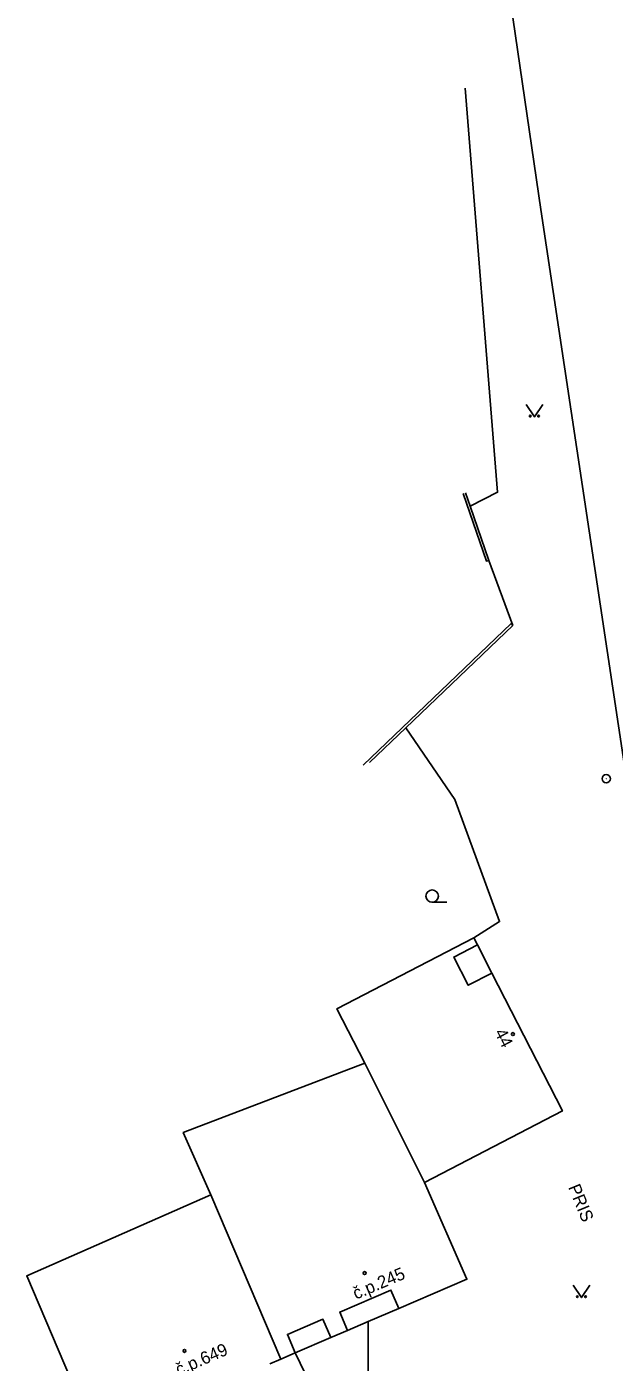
# Model space of a CAD drawing. Extents: x -577457 to -568404, y -1208466 to -1201387.
# Drawn here: x -574806.3 to -574771, y -1204115.5 to -1204035.2 of the extents above; entities that cross this region are included whole.
import ezdxf

# ---------------------------------------------------------------- set-up
doc = ezdxf.new("R2010")
doc.units = 0
for name, color, linetype in [('BUDOVY_MĚŘ', 7, 'Continuous'), ('BUDOVY_NEMĚŘ', 7, 'Continuous'), ('POMOC_POPIS', 7, 'Continuous'), ('ROZHRANÍ_PLOCH', 7, 'Continuous'), ('ZN_BUDOV', 7, 'Continuous'), ('ZN_DOPLŇKOVÉ', 7, 'Continuous'), ('ZN_KULTUR', 7, 'Continuous'), ('Č_POPIS_ORIENT', 7, 'Continuous')]:
    doc.layers.add(name, color=color, linetype=linetype)

msp = doc.modelspace()

# ---------------------------------------------------------------- linework, layer by layer
at = {"layer": 'BUDOVY_MĚŘ'}
for points in [[(-574779.19, -1204090.44), (-574780.62, -1204091.17), (-574779.75, -1204092.86), (-574778.33, -1204092.13)], [(-574779.41, -1204090.02), (-574779.19, -1204090.44)], [(-574779.19, -1204090.44), (-574778.33, -1204092.13)], [(-574778.33, -1204092.13), (-574774.08, -1204100.42), (-574782.39, -1204104.73)], [(-574782.39, -1204104.73), (-574779.83, -1204110.55), (-574783.92, -1204112.3)], [(-574787.01, -1204113.63), (-574787.48, -1204112.52), (-574784.4, -1204111.2), (-574783.92, -1204112.3)], [(-574783.92, -1204112.3), (-574785.76, -1204113.09)], [(-574790.16, -1204114.98), (-574790.63, -1204113.87), (-574788.49, -1204112.95), (-574788.02, -1204114.06)], [(-574785.76, -1204113.09), (-574787.01, -1204113.63)], [(-574787.01, -1204113.63), (-574788.02, -1204114.06)], [(-574788.02, -1204114.06), (-574790.16, -1204114.98)], [(-574791.03, -1204115.35), (-574791.69, -1204115.63)], [(-574790.16, -1204114.98), (-574791.03, -1204115.35)]]:
    msp.add_lwpolyline(points, dxfattribs=at)
at = {"layer": 'BUDOVY_NEMĚŘ'}
for points in [[(-574785.97, -1204097.56), (-574787.66, -1204094.29), (-574779.41, -1204090.02)], [(-574791.03, -1204115.35), (-574795.24, -1204105.48), (-574796.89, -1204101.73), (-574796.21, -1204101.47), (-574785.97, -1204097.56)], [(-574782.39, -1204104.73), (-574785.97, -1204097.56)], [(-574802.14, -1204120.15), (-574806.31, -1204110.35), (-574795.24, -1204105.48)]]:
    msp.add_lwpolyline(points, dxfattribs=at)
at = {"layer": 'ROZHRANÍ_PLOCH'}
for points in [[(-574781.43, -1204008.33), (-574780.13, -1204013.6), (-574775.38, -1204046.2), (-574769.96, -1204082.19)], [(-574783.05, -1204124.64), (-574785.74, -1204119.07), (-574785.76, -1204113.09)], [(-574790.16, -1204114.98), (-574785.07, -1204125.51)]]:
    msp.add_lwpolyline(points, dxfattribs=at)
at = {"layer": 'ZN_BUDOV'}
for centre in [(-574777.06, -1204095.8), (-574785.98, -1204110.18), (-574796.82, -1204114.86)]:
    msp.add_circle(centre, 0.0875, dxfattribs=at)
at = {"layer": 'ZN_DOPLŇKOVÉ'}
for points in [[(-574779.93, -1204038.9), (-574777.98, -1204063.21), (-574779.64, -1204064.04)], [(-574780.05, -1204063.28), (-574778.66, -1204067.35), (-574778.52, -1204067.31)], [(-574779.91, -1204063.24), (-574779.64, -1204064.04)], [(-574779.64, -1204064.04), (-574778.52, -1204067.31)], [(-574778.52, -1204067.31), (-574777.07, -1204071.22)], [(-574777.07, -1204071.22), (-574777.17, -1204071.11), (-574786.07, -1204079.62)], [(-574777.07, -1204071.22), (-574783.51, -1204077.38)], [(-574783.51, -1204077.38), (-574785.69, -1204079.46)], [(-574783.51, -1204077.38), (-574780.55, -1204081.69)], [(-574780.55, -1204081.69), (-574777.86, -1204089.03), (-574779.41, -1204090.02)]]:
    msp.add_lwpolyline(points, dxfattribs=at)
for radius in [0.25, 0.0005]:
    msp.add_circle((-574771.45, -1204080.44), radius, dxfattribs=at)
at = {"layer": 'ZN_KULTUR'}
msp.add_line((-574781.92, -1204087.875), (-574781.045, -1204087.875), dxfattribs=at)
for points in [[(-574776.27, -1204057.93), (-574775.77, -1204058.68), (-574775.27, -1204057.93)], [(-574773.44, -1204110.9), (-574772.94, -1204111.65), (-574772.44, -1204110.9)]]:
    msp.add_lwpolyline(points, dxfattribs=at)
for centre, radius in [((-574776.02, -1204058.63), 0.05), ((-574775.52, -1204058.63), 0.05), ((-574781.92, -1204087.5), 0.375), ((-574773.19, -1204111.6), 0.05), ((-574772.69, -1204111.6), 0.05)]:
    msp.add_circle(centre, radius, dxfattribs=at)

# ---------------------------------------------------------------- texts
at = {"layer": 'POMOC_POPIS'}
msp.add_text('PRIS', height=0.75, rotation=292.19003, dxfattribs=at).set_placement((-574773.75, -1204105.01))
at = {"layer": 'Č_POPIS_ORIENT'}
for s, rotation, p in [('44', 297.09999, (-574778.19, -1204095.7)), ('č.p.245', 23.15999, (-574786.5, -1204111.78)), ('č.p.649', 23.39003, (-574797.16, -1204116.36))]:
    msp.add_text(s, height=0.75, rotation=rotation, dxfattribs=at).set_placement(p)

doc.saveas('drawing.dxf')
